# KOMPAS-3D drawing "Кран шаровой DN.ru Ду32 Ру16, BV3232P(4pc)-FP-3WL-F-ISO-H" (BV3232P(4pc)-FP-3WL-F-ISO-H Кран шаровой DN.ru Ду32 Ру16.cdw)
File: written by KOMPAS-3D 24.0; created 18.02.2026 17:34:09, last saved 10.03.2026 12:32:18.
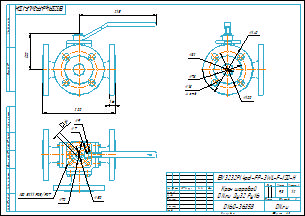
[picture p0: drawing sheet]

Document properties: Автор: R2D2; Форматы листов документа: A3; Полное имя файла: BV3232P(4pc)-FP-3WL-F-ISO-H Кран шаровой DN.ru Ду32 Ру16.m3d; Масса: 9.3; Наименование: Кран шаровой DN.ru Ду32 Ру16; Количество листов документа: 1; Примечание: D160-36358

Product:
- Part/product: Кран шаровой DN.ru Ду32 Ру16  | designation BV3232P(4pc)-FP-3WL-F-ISO-H
    Масса: 9.3
    Раздел спецификации: Прочие изделия
    Примечание: D160-36358

Views: Вид 1, Спереди, Проекционный вид 2
Referenced files in E:\Работа\Зайцев\BV3232P(4pc)-FP-3WL-F-ISO-H Кран шаровой DN.ru Ду15-100 Ру16\DN32\: BV3232P(4pc)-FP-3WL-F-ISO-H Кран шаровой DN.ru Ду32 Ру16.m3d
Referenced files in E:\Работа\Зайцев\Для компаса\: чертеж DN.ru А3.cdt
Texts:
  BV3232P(4pc)-FP-3WL-F-ISO-H
  чертеж DN.ru А3.cdt
  Кран шаровой
  DN.ru Ду32 Ру16
  Кран шаровой DN.ru Ду32 Ру16
  BV3232P(4pc)-FP-3WL-F-ISO-H Кран шаровой DN.ru Ду32 Ру16
Dimensions and other numbers on the sheet: 0; 3; 2; 4; 215; 100; 200; 16; 140; 78; 18; 4 отв.; 32; 1:2; 1; 9,3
